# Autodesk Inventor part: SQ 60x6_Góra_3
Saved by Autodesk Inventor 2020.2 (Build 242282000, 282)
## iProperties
Created: 2006-08
Part Number: SQ 60x6_Góra_3
Material: Ogólny
Document SubType Name: Modeling
Designer: F.Stasiak
Manufacturer: Standard
Standards Organization: Custom
Stock Number: DIN EN 10210-2 SQ 60x6
Density: 1 g/cm^3
Appearance: Domyślna
Manager: www.cadconsulting.pl
Company: Fabian Stasiak CAD Consulting
G_L: 1000,0 mm
G_W: 60,000 mm
G_H: 60,000 mm
AFG_Item: 60 x 60 x 6
Author: F.Stasiak
Subject: Zbiór ćwiczeń. Autodesk Inventor 2020. Kurs podstawowy
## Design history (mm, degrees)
sketch "AFG_Detailed"
  geometry: L1 (48, 54)-(12, 54); L2 (6, 48)-(6, 12); L3 (12, 6)-(48, 6); L4 (54, 12)-(54, 48); L5 (48, 60)-(12, 60); L6 (0, 48)-(0, 12); L7 (12, 0)-(48, 0); L8 (60, 12)-(60, 48); A1 r 6 centre (48, 48) between (54, 48) and (48, 54); A2 r 12 centre (48, 48) between (60, 48) and (48, 60); A3 r 6 centre (48, 12) between (48, 6) and (54, 12); A4 r 12 centre (48, 12) between (48, 0) and (60, 12); A5 r 12 centre (12, 12) between (0, 12) and (12, 0); A6 r 6 centre (12, 12) between (6, 12) and (12, 6); A7 r 6 centre (12, 48) between (12, 54) and (6, 48); A8 r 12 centre (12, 48) between (12, 60) and (0, 48); 4 further points
  constraints: 16 end point, 16 point on circle, 16 tangent, 8 centre point, 6 point on line, 4 parallel, 2 perpendicular, 1 vertical
  dimensions: "d15" = 60 distance of point (0, 0) point (60, 0) (= GEO_B); "d16" = 6 distance between parallel lines of L7 L3 (= GEO_S); "d17" = 6 distance between parallel lines of L8 L4 (= GEO_S); "d18" = 6 distance between parallel lines of L5 L1 (= GEO_S); "d19" = 6 distance between parallel lines of L6 L2 (= GEO_S); "d20" = 30 distance from line of point (30, 30) L7 (= 0.5 x GEO_H); "d30" = 6 radius of A1 (= GEO_R1 - GEO_S); "GEO_R1" = 12 radius of A2; "d32" = 6 radius of A3 (= GEO_R1 - GEO_S); "d33" = 12 radius of A4 (= GEO_R1); "d34" = 12 radius of A5 (= GEO_R1); "d35" = 6 radius of A6 (= GEO_R1 - GEO_S); "d36" = 6 radius of A7 (= GEO_R1 - GEO_S); "d37" = 12 radius of A8 (= GEO_R1); "d38" = 30 distance from line of L6 point (30, 30) (= 0.5 x GEO_B); "d39" = 60 distance between parallel lines of L7 L5 (= GEO_H)
sketch "AFG_Medium"
  geometry: L1 (54, 54)-(6, 54); L2 (6, 54)-(6, 6); L3 (6, 6)-(54, 6); L4 (54, 6)-(54, 54); L5 (60, 60)-(0, 60); L6 (0, 60)-(0, 0); L7 (0, 0)-(60, 0); L8 (60, 0)-(60, 60); 1 further point
  constraints: 16 end point, 4 parallel, 2 perpendicular, 1 vertical
  dimensions: "GEO_B" = 60 distance of L6.end L7.end; "GEO_S" = 6 distance between parallel lines of L7 L3; "d5" = 6 distance between parallel lines of L8 L4 (= GEO_S); "d6" = 6 distance between parallel lines of L5 L1 (= GEO_S); "d7" = 6 distance between parallel lines of L6 L2 (= GEO_S); "d12" = 30 distance from line of point (30, 30) L7 (= 0.5 x GEO_H); "d40" = 60 distance between parallel lines of L7 L5 (= GEO_H); "d41" = 30 distance from line of L6 point (30, 30) (= 0.5 x GEO_B)
sketch "AFG_Simplified"
  geometry: L1 (60, 60)-(0, 60); L2 (0, 60)-(0, 0); L3 (0, 0)-(60, 0); L4 (60, 0)-(60, 60); 1 further point
  constraints: 8 end point, 2 parallel, 1 perpendicular, 1 vertical
  dimensions: "d23" = 60 distance of L2.end L3.end (= GEO_B); "d28" = 30 distance from line of point (30, 30) L3 (= 0.5 x GEO_H); "d42" = 60 distance between parallel lines of L3 L1 (= GEO_H); "d43" = 30 distance from line of point (30, 30) L2 (= 0.5 x GEO_B)
derived "Szkielet podstawy.ipt"
  sketch "Szkic1"
    geometry: L1 (0, 0)-(1500, 0) reference; L2 (1500, 0)-(1500, 1000) reference; L3 (1500, 1000)-(0, 1000) reference; L4 (0, 1000)-(0, 0) reference
  sketch "Szkic2"
    geometry: L1 (0, 1000)-(0, 0) reference; L2 (0, 0)-(1500, 0) reference; L3 (1500, 0)-(1500, 1000) reference; L4 (500, 1000)-(1500, 1000) reference; L5 (1500, 1000)-(1500, 0) reference; L6 (1500, 0)-(500, 0) reference; L7 (500, 0)-(500, 1000) reference; L8 (1500, 1000)-(0, 1000) reference
node "AFG_StartWorkPoint_SQ 60x6_Góra_3"
node "AFG_EndWorkPoint_SQ 60x6_Góra_3"
node "AFG_HelpAxis"
node "AFG_HelpStart"
node "AFG_HelpEnd"
node "AFG_Midplane"
  node "AFG_Startplane"
  node "AFG_EndPlane"
node "AFG_Profile_AxisX_for_External_Matrix"
extrude "AFG_Detailed_SQ 60x6_Góra_3" join sketch "AFG_Detailed" stored distance "d49" = 0.13; taper "d50" = 0 deg
extrude "AFG_Simplified_SQ 60x6_Góra_3" join sketch "AFG_Simplified" stored distance "d51" = 0.13; taper "d52" = 0 deg
node "AFG_StartWorkPoint_SQ 60x6_Góra_2"
node "AFG_EndWorkPoint_SQ 60x6_Góra_2"
node "AFG_STARTCUTPLANE_SQ 60x6_Góra_3"
node "AFG_StartWorkPoint_SQ 60x6_Góra_4"
node "AFG_EndWorkPoint_SQ 60x6_Góra_4"
node "AFG_ENDCUTPLANE_SQ 60x6_Góra_3"
node "Bryła1"
node "Korpusy bryłowe"
node "Korpusy powierzchniowe"
other parameters: "GEO_H" = 60, "AFG_Origin_X" = 0 (= 0 x GEO_B) [user parameter], "AFG_Origin_Y" = 0 (= 0 x GEO_H) [user parameter], "AFG_IP_X2" = 0 (= 0 x GEO_B) [user parameter], "AFG_IP_Y4" = 0 (= 0 x GEO_H) [user parameter], "AFG_IP_X6" = 0 (= 0 x GEO_B) [user parameter], "AFG_IP_Y8" = 0 (= 0 x GEO_H) [user parameter], "d47" = 0, "d48" = 0, "G_L" = 1000 [user parameter], "d55" = 0, "d58" = 0
